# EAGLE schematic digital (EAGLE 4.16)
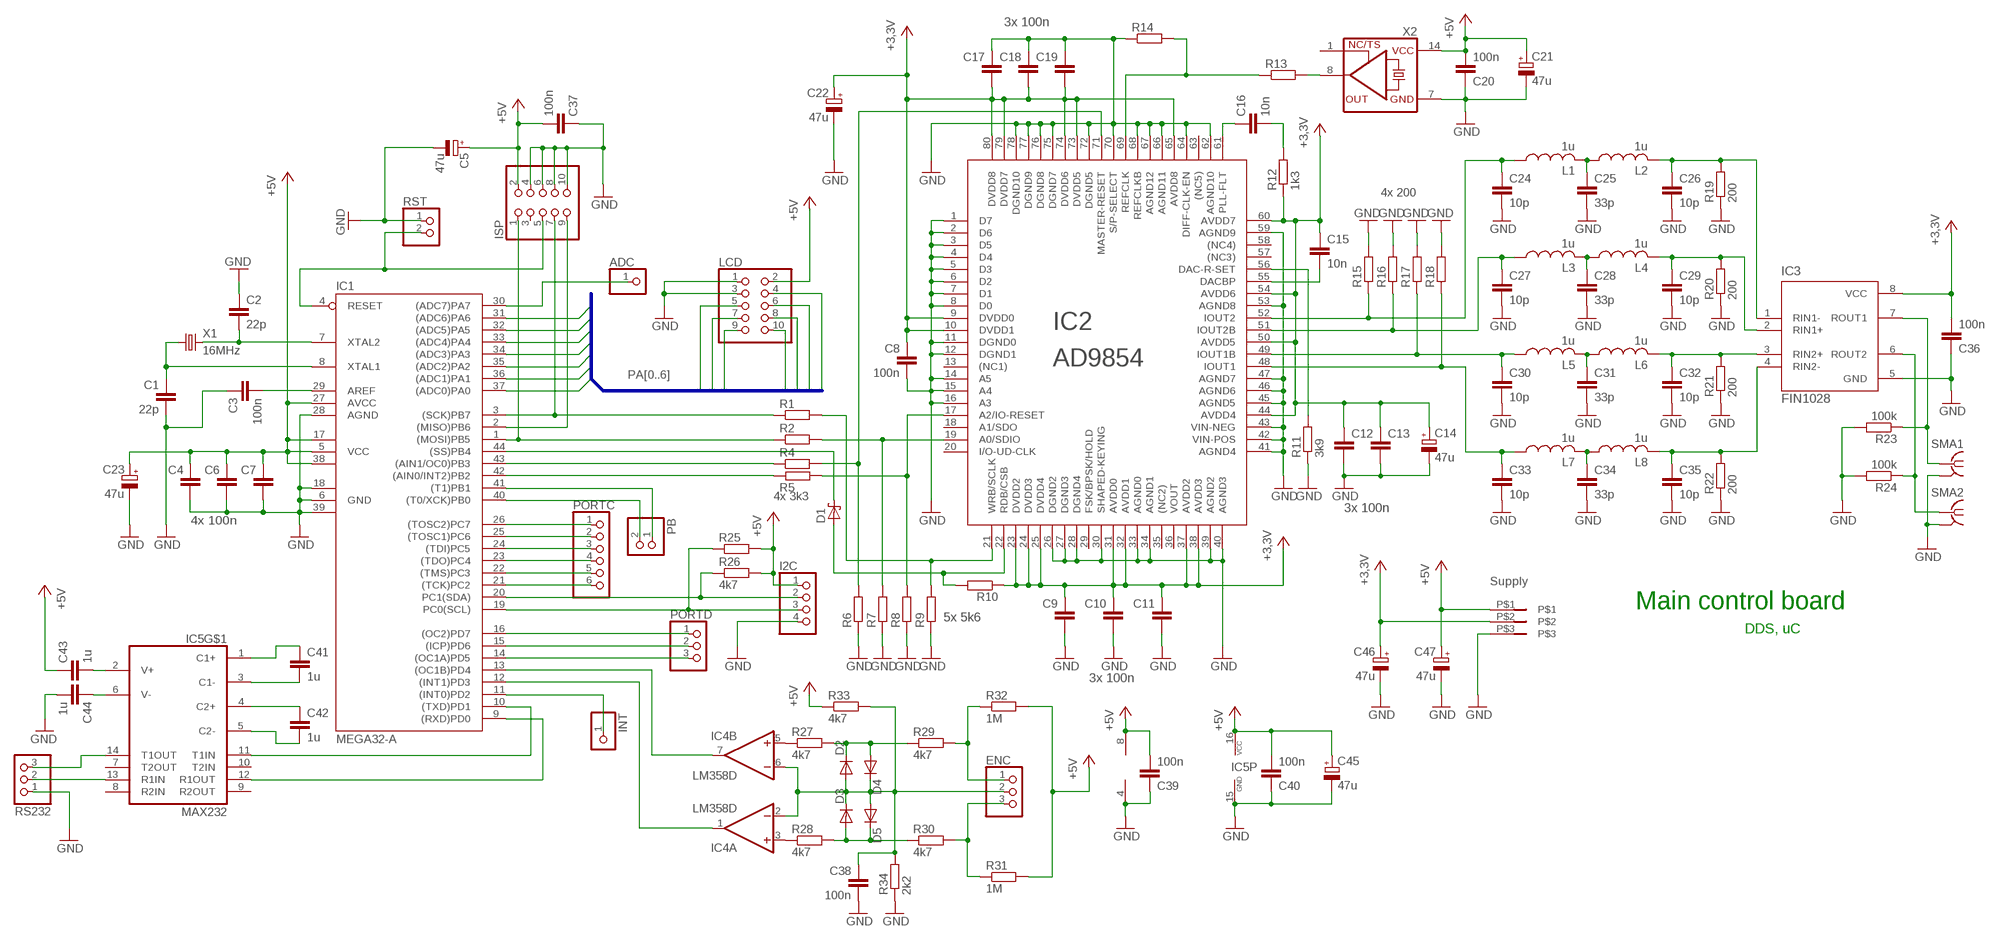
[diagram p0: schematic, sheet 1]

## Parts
ADC  PINHD-1X1  [1X01]
C1  22p  C-EUC0805  [C0805]
C2  22p  C-EUC0805  [C0805]
C3  100n  C-EUC0805  [C0805]
C4  C-EUC1206  [C1206]
C5  47u  CPOL-EUC  [PANASONIC_C]
C6  C-EUC1206  [C1206]
C7  C-EUC1206  [C1206]
C8  100n  C-EUC1206  [C1206]
C9  C-EUC1206  [C1206]
C10  C-EUC1206  [C1206]
C11  C-EUC1206  [C1206]
C12  C-EUC1206  [C1206]
C13  C-EUC1206  [C1206]
C14  47u  CPOL-EUC  [PANASONIC_C]
C15  10n  C-EUC0805  [C0805]
C16  10n  C-EUC0805  [C0805]
C17  C-EUC1206  [C1206]
C18  C-EUC1206  [C1206]
C19  C-EUC1206  [C1206]
C20  100n  C-EUC1206  [C1206]
C21  47u  CPOL-EUC  [PANASONIC_C]
C22  47u  CPOL-EUC  [PANASONIC_C]
C23  47u  CPOL-EUC  [PANASONIC_C]
C24  10p  C-EUC1206  [C1206]
C25  33p  C-EUC1206  [C1206]
C26  10p  C-EUC1206  [C1206]
C27  10p  C-EUC1206  [C1206]
C28  33p  C-EUC1206  [C1206]
C29  10p  C-EUC1206  [C1206]
C30  10p  C-EUC1206  [C1206]
C31  33p  C-EUC1206  [C1206]
C32  10p  C-EUC1206  [C1206]
C33  10p  C-EUC1206  [C1206]
C34  33p  C-EUC1206  [C1206]
C35  10p  C-EUC1206  [C1206]
C36  100n  C-EUC1206  [C1206]
C37  100n  C-EUC1206  [C1206]
C38  100n  C-EUC1206  [C1206]
C39  100n  C-EUC1206  [C1206]
C40  100n  C-EUC1206  [C1206]
C41  1u  C-EUC1206  [C1206]
C42  1u  C-EUC1206  [C1206]
C43  1u  C-EUC1206  [C1206]
C44  1u  C-EUC1206  [C1206]
C45  47u  CPOL-EUC  [PANASONIC_C]
C46  47u  CPOL-EUC  [PANASONIC_C]
C47  47u  CPOL-EUC  [PANASONIC_C]
D1  SCHOTTKY-DIODESMD  [SMB]
D2  PMLL4150  [SOD80C]
D3  PMLL4150  [SOD80C]
D4  PMLL4150  [SOD80C]
D5  PMLL4150  [SOD80C]
ENC  PINHD-1X3  [1X03]
I2C  PINHD-1X4  [1X04]
IC1  MEGA32-A  [TQFP44]
IC2  AD9854  AD9854-(TQFP)  [TQFP80-917]
IC3  FIN1028  [SO08]
IC4  LM358D  [SO08]
IC5  MAX232  [SO16]
INT  PINHD-1X1  [1X01]
ISP  PINHD-2X5  [2X05]
L1  1u  L-US0207/2V  [0207/2V]
L2  1u  L-US0207/2V  [0207/2V]
L3  1u  L-US0207/2V  [0207/2V]
L4  1u  L-US0207/2V  [0207/2V]
L5  1u  L-US0207/2V  [0207/2V]
L6  1u  L-US0207/2V  [0207/2V]
L7  1u  L-US0207/2V  [0207/2V]
L8  1u  L-US0207/2V  [0207/2V]
LCD  PINHD-2X5  [2X05]
PB  PINHD-1X2  [1X02]
PORTC  PINHD-1X6  [1X06]
PORTD  PINHD-1X3  [1X03]
R1  R-EU_R1206  [R1206]
R2  R-EU_R1206  [R1206]
R4  R-EU_R1206  [R1206]
R5  R-EU_R1206  [R1206]
R6  R-EU_R1206  [R1206]
R7  R-EU_R1206  [R1206]
R8  R-EU_R1206  [R1206]
R9  R-EU_R1206  [R1206]
R10  R-EU_R1206  [R1206]
R11  3k9  R-EU_R1206  [R1206]
R12  1k3  R-EU_R1206  [R1206]
R13  R-EU_R1206  [R1206]
R14  R-EU_R1206  [R1206]
R15  R-EU_R1206  [R1206]
R16  R-EU_R1206  [R1206]
R17  R-EU_R1206  [R1206]
R18  R-EU_R1206  [R1206]
R19  200  R-EU_R1206  [R1206]
R20  200  R-EU_R1206  [R1206]
R21  200  R-EU_R1206  [R1206]
R22  200  R-EU_R1206  [R1206]
R23  100k  R-EU_R1206  [R1206]
R24  100k  R-EU_R1206  [R1206]
R25  R-EU_R1206  [R1206]
R26  4k7  R-EU_R1206  [R1206]
R27  4k7  R-EU_R1206  [R1206]
R28  4k7  R-EU_R1206  [R1206]
R29  4k7  R-EU_R1206  [R1206]
R30  4k7  R-EU_R1206  [R1206]
R31  1M  R-EU_R1206  [R1206]
R32  1M  R-EU_R1206  [R1206]
R33  4k7  R-EU_R1206  [R1206]
R34  2k2  R-EU_R1206  [R1206]
RS232  PINHD-1X3  [1X03]
RST  PINHD-1X2  [1X02]
SMA1  BU-SMA-V  [BU-SMA-V]
SMA2  BU-SMA-V  [BU-SMA-V]
U$2  RIACON-3  [RIACON-3]
X1  16MHz  CRYTALHC49UP  [HC49UP]
X2  XO-14  [DIL14S]

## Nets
GND: RS232.1 U$2.P$3
N$1: IC2.21(WRB/SCLK) R1.2 R9.2
N$3: IC2.69(REFCLK) R13.1 R14.2
N$4: D1.C IC1.44((SS)PB4)
N$5: D1.A IC2.22(RDB/CSB) R10.2
N$6: C16.2 R12.2
N$7: IC2.71(MASTER-RESET) R4.2 R6.2
N$8: R13.2 X2.8(OUT)
N$11: IC4.5(B:+IN) R27.1
N$12: IC2.56(DAC-R-SET) R11.2
N$14: C15.2 IC2.55(DACBP)
N$15: C28.1 L3.2 L4.1
N$16: IC4.3(A:+IN) R28.1
N$17: C2.2 IC1.7(XTAL2) X1.2
N$18: C1.1 IC1.8(XTAL1) X1.1
N$19: IC1.10((TXD)PD1) IC5.11(T1IN)
N$20: IC1.9((RXD)PD0) IC5.12(R1OUT)
N$21: C3.2 IC1.29(AREF)
N$23: I2C.3 IC1.19(PC0(SCL)) R25.1
N$24: IC2.17(A2/IO-RESET) R5.2 R8.2
N$25: IC1.43((AIN1/OC0)PB3) R4.1
N$26: IC1.42((AIN0/INT2)PB2) R5.1
N$27: C16.1 IC2.61(PLL-FLT)
N$29: C27.1 IC2.51(IOUT2B) L3.1 R16.1
N$30: C30.1 IC2.49(IOUT1B) L5.1 R17.1
N$31: C33.1 IC2.48(IOUT1) L7.1 R18.1
N$32: C25.1 L1.2 L2.1
N$33: C26.1 IC3.1(RIN1-) L2.2 R19.2
N$34: C31.1 L5.2 L6.1
N$35: C32.1 IC3.3(RIN2+) L6.2 R21.2
N$36: C29.1 IC3.2(RIN1+) L4.2 R20.2
N$37: C34.1 L7.2 L8.1
N$38: IC3.7(ROUT1) R23.1 SMA1.1
N$39: IC3.6(ROUT2) R24.1 SMA2.1
N$43: D2.C D4.A R27.2 R29.1
N$44: D3.A D5.C R28.2 R30.1
N$47: ENC.1 R29.2 R32.1
N$48: ENC.3 R30.2 R31.1
N$50: IC1.23((TDO)PC4) PORTC.4
N$51: IC1.13((OC1B)PD4) IC4.7(B:OUT)
N$52: IC1.12((INT1)PD3) IC4.1(A:OUT)
N$53: IC1.24((TDI)PC5) PORTC.3
N$54: IC1.25((TOSC1)PC6) PORTC.2
N$55: IC1.26((TOSC2)PC7) PORTC.1
N$56: IC1.14((OC1A)PD5) PORTD.3
N$57: IC1.15((ICP)PD6) PORTD.2
N$58: IC1.16((OC2)PD7) PORTD.1
N$59: ADC.1 IC1.30((ADC7)PA7)
N$60: IC1.11((INT0)PD2) INT.1
N$61: IC1.40((T0/XCK)PB0) PB.2
N$62: IC1.41((T1)PB1) PB.1
N$63: IC5.13(R1IN) RS232.2
N$64: C41.2 IC5.3(C1-)
N$65: C41.1 IC5.1(C1+)
N$66: C42.1 IC5.4(C2+)
N$67: C42.2 IC5.5(C2-)
N$68: C43.2 IC5.2(V+)
N$69: C44.1 IC5.6(V-)
N$70: IC5.14(T1OUT) RS232.3
N$105: C24.1 IC2.52(IOUT2) L1.1 R15.1
N$123: C35.1 IC3.4(RIN2-) L8.2 R22.2
N$154: IC1.22((TMS)PC3) PORTC.5
N$155: IC1.21((TCK)PC2) PORTC.6
N$205: C4.1 C5.+ C6.1 C7.1 C20.2 C21.+ C23.+ C37.2 C39.2 C40.2 C43.1 C45.+ C47.+ I2C.1 IC1.5(VCC) IC1.17(VCC1) IC1.27(AVCC) IC1.38(VCC2) IC4.8(P:V+) IC5.16(P:VCC) ISP.2 LCD.2 R25.2 R26.2 R31.2 R32.2 R33.1 U$2.P$1 X2.14(VCC) ; supply symbol labelled +5V
N$211: I2C.2 IC1.20(PC1(SDA)) R26.1
N$217: IC1.2((MISO)PB6) ISP.9
N$218: IC1.3((SCK)PB7) ISP.7 R1.1
N$220: IC1.4(RESET) ISP.5 RST.2
N$241: C38.1 D2.A D3.C D4.C D5.A ENC.2 IC4.2(A:-IN) IC4.6(B:-IN) R33.2 R34.2
N$307: C8.1 C9.1 C10.1 C11.1 C12.1 C13.1 C14.+ C15.1 C17.2 C18.2 C19.2 C22.+ C36.2 C46.+ IC2.9(DVDD0) IC2.10(DVDD1) IC2.23(DVDD2) IC2.24(DVDD3) IC2.25(DVDD4) IC2.31(AVDD0) IC2.32(AVDD1) IC2.37(AVDD2) IC2.38(AVDD3) IC2.44(AVDD4) IC2.50(AVDD5) IC2.54(AVDD6) IC2.60(AVDD7) IC2.65(AVDD8) IC2.73(DVDD5) IC2.74(DVDD6) IC2.79(DVDD7) IC2.80(DVDD8) IC3.8(VCC) R10.1 R12.1 U$2.P$2 ; supply symbol labelled +3,3V
N$318: IC2.19(A0/SDIO) R2.2 R7.2
N$356: IC1.1((MOSI)PB5) ISP.1 R2.1
N$360: C1.2 C2.1 C3.1 C4.2 C5.- C6.2 C7.2 C8.2 C9.2 C10.2 C11.2 C12.2 C13.2 C14.- C17.1 C18.1 C19.1 C20.1 C21.- C22.- C23.- C24.2 C25.2 C26.2 C27.2 C28.2 C29.2 C30.2 C31.2 C32.2 C33.2 C34.2 C35.2 C36.1 C37.1 C38.2 C39.1 C40.1 C44.2 C45.- C46.- C47.- I2C.4 IC1.6(GND) IC1.18(GND1) IC1.28(AGND) IC1.39(GND2) IC2.1(D7) IC2.2(D6) IC2.3(D5) IC2.4(D4) IC2.5(D3) IC2.6(D2) IC2.7(D1) IC2.8(D0) IC2.11(DGND0) IC2.12(DGND1) IC2.14(A5) IC2.15(A4) IC2.16(A3) IC2.26(DGND2) IC2.27(DGND3) IC2.28(DGND4) IC2.30(SHAPED-KEYING) IC2.33(AGND0) IC2.34(AGND1) IC2.39(AGND2) IC2.40(AGND3) IC2.41(AGND4) IC2.42(VIN-POS) IC2.43(VIN-NEG) IC2.45(AGND5) IC2.46(AGND6) IC2.47(AGND7) IC2.53(AGND8) IC2.59(AGND9) IC2.62(AGND10) IC2.64(DIFF-CLK-EN) IC2.66(AGND11) IC2.67(AGND12) IC2.68(REFCLKB) IC2.70(S/P-SELECT) IC2.72(DGND5) IC2.75(DGND7) IC2.76(DGND8) IC2.77(DGND9) IC2.78(DGND10) IC3.5(GND) IC4.4(P:V-) IC5.15(P:GND) ISP.4 ISP.6 ISP.8 ISP.10 LCD.1 LCD.3 R6.1 R7.1 R8.1 R9.1 R11.1 R14.1 R15.2 R16.2 R17.2 R18.2 R19.1 R20.1 R21.1 R22.1 R23.2 R24.2 R34.1 RST.1 SMA1.2(GND) SMA2.2(GND) X2.7(GND) ; supply symbol labelled GND
PA0: IC1.37((ADC0)PA0) LCD.10
PA1: IC1.36((ADC1)PA1) LCD.9
PA2: IC1.35((ADC2)PA2) LCD.8
PA3: IC1.34((ADC3)PA3) LCD.7
PA4: IC1.33((ADC4)PA4) LCD.6
PA5: IC1.32((ADC5)PA5) LCD.5
PA6: IC1.31((ADC6)PA6) LCD.4
Unconnected: IC2.13((NC1)) IC2.18(A1/SDO) IC2.20(I/O-UD-CLK) IC2.29(FSK/BPSK/HOLD) IC2.35((NC2)) IC2.36(VOUT) IC2.57((NC3)) IC2.58((NC4)) IC2.63((NC5)) IC5.7(T2OUT) IC5.8(R2IN) IC5.9(R2OUT) IC5.10(T2IN) ISP.3 X2.1(TS)

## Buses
PA[0..6]

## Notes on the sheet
- 3x 100n
- 4x 200
- 4x 3k3
- 3x 100n
- 4x 100n
- Supply
- Main control board
- 5x 5k6
- DDS, uC
- 3x 100n

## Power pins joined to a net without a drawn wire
N$360: SMA1.3(GND) SMA1.4(GND) SMA1.5(GND) SMA2.3(GND) SMA2.4(GND) SMA2.5(GND)

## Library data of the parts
ADC INT = pinhead:PINHD-1X1: PIN HEADER
C1-C4 C6-C13 C15-C20 C24-C44 = rcl:C-EU: CAPACITOR, European symbol
C5 C14 C21-C23 C45-C47 = rcl:CPOL-EU: POLARIZED CAPACITOR, European symbol
D1 = diode:SCHOTTKY-DIODE: Schottky Diode
D2-D5 = diode:PMLL4150: DIODE
ENC PORTD RS232 = pinhead:PINHD-1X3: PIN HEADER
I2C = pinhead:PINHD-1X4: PIN HEADER
IC1 = avr:MEGA32: MICROCONTROLLER 32 Kbytes FLASH 2 Kbytes SRAM 1 Kbytes EEPROM USART 8-channel 10 bit ADC
IC2 = receiver:AD9854: CMOS 300 MSPS Quadrature Complete DDS
IC3 = receiver:FIN1028: FIN1028/MAX9113 3.3V LVDS 2-bit high speed differential receiver
IC4 = linear:LM358: OP AMP also LM158; LM258; LM2904 Source: http://cache.national.com/ds/LM/LM158.pdf
IC5 = receiver:MAX232: RS232 TRANSEIVER
ISP LCD = pinhead:PINHD-2X5: PIN HEADER
L1-L8 = rcl:L-US: INDUCTOR, American symbol
PB RST = pinhead:PINHD-1X2: PIN HEADER
PORTC = pinhead:PINHD-1X6: PIN HEADER
R1 R2 R4-R34 = rcl:R-EU_: RESISTOR, European symbol
SMA1 SMA2 = con-coax:BU-SMA-V: FEMALE SMA CONNECTOR Radiall distributor RS 112-3794
U$2 = con-riacon:RIACON-3
X1 = crystal:CRYTAL: CRYSTAL
X2 = crystal:XO-: CRYSTAL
